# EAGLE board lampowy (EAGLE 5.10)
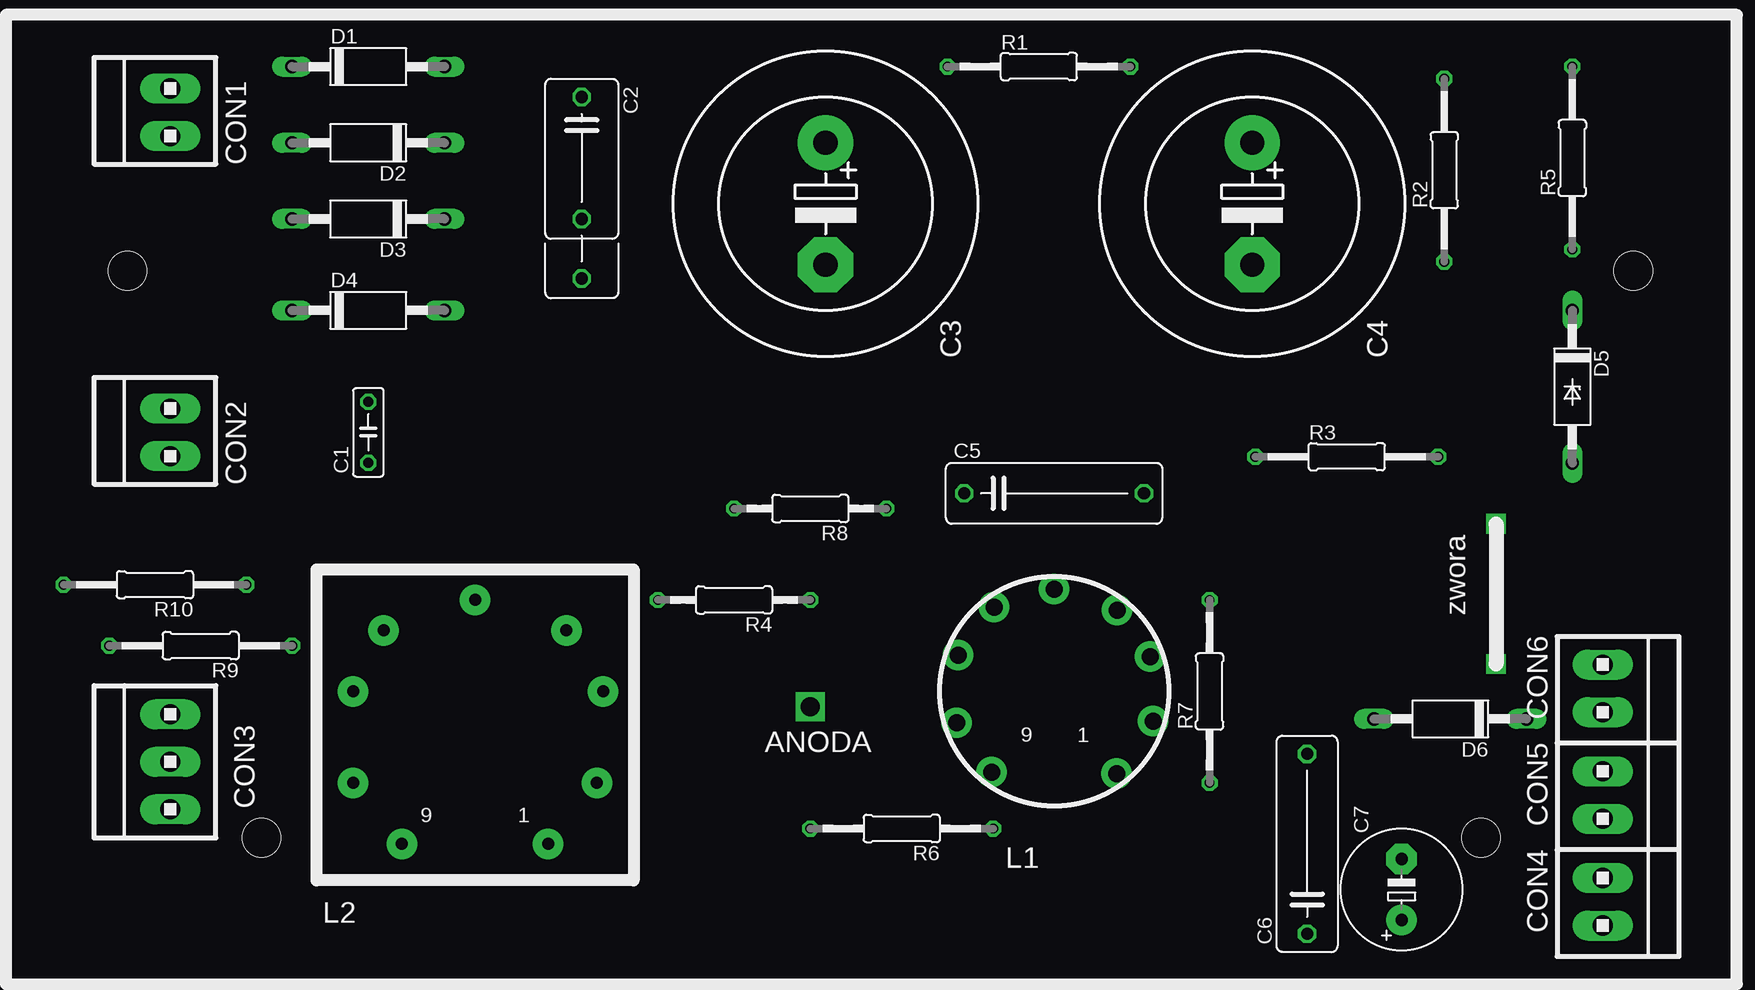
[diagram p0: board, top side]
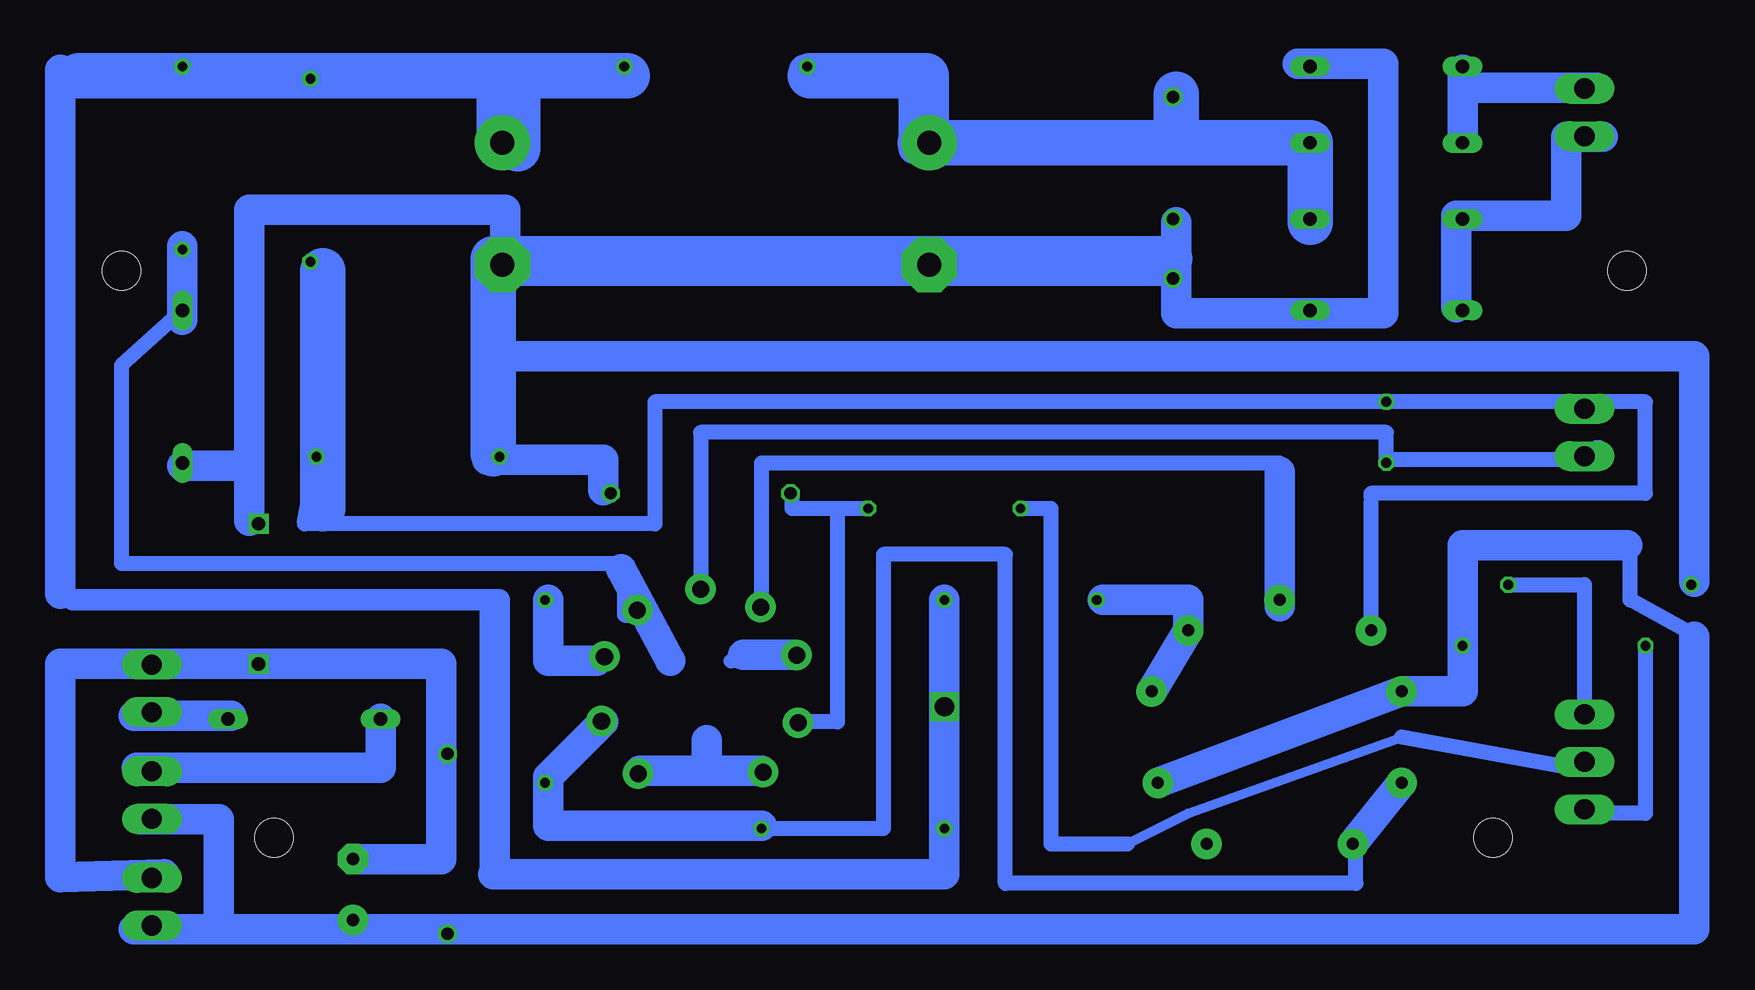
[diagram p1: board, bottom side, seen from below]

No outline drawn. Coordinates in mm, seen from the top.
Copper layers (1*16): Top 0.035mm / dielectric 1.5mm / Bottom 0.035mm
Design rules "default": minimum track width 10mil, minimum drill 24mil, track to track 8mil, track to pad 8mil, pad to pad 8mil, via to via 8mil, smd to smd 8mil, copper to edge 40mil, drill to drill 8mil, minimum pad ring 10mil, minimum via ring 8mil, stop-mask expansion 4mil, vias tented up to drill 0mil, thermal gap 10mil
Holes 3.2 mm at 10.16,59.44 135.64,59.44 122.94,12.19 21.34,12.19

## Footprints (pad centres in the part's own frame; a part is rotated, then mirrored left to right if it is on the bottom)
C050-025X075 = drill 0.813 octagon: 1 -2.54,0; 2 2.54,0
C102_152-062X184 = drill 1.016 octagon: 1 -5.08,0; 2 5.08,0; 3 10.033,0
EB25D = drill 2.007 pad 4.597 round: + -5.08,0 | drill 2.007 pad 4.597 octagon: - 5.08,0
C150-054X183 = drill 1.016 octagon: 1 -7.493,0; 2 7.493,0
E5-10,5 = drill 1.016 pad 2.54 round: + -2.54,0 | drill 1.016 pad 2.54 octagon: - 2.54,0
1X2MTA = drill 1.676 long: 1 1.981,0; 2 -1.981,0
1X3MTA = drill 1.676 long: 1 3.937,0; 2 -0.025,0; 3 -3.988,0
P1-12E = drill 1.118 long: A 6.35,0; C -6.35,0
P1Z12 = drill 1.118 long: A 6.35,0; C -6.35,0
NOVAL = drill 1.422 pad 2.54 round: 1 5.207,-6.858; 2 8.254,-2.484; 3 8.004,2.893; 4 5.258,6.77; 5 0,8.524; 6 -5.004,7.024; 7 -8.004,3.02; 8 -8.127,-2.611; 9 -5.207,-6.731
MAGNOWAL = drill 1 pad 2.54 round: P$1 0,-10.16; P$2 6.096,10.16; P$3 -6.096,10.16; P$4 -10.16,5.08; P$5 10.16,5.08; P$6 10.16,-2.54; P$7 -10.668,-2.54; P$8 -7.62,-7.62; P$9 7.62,-7.62
0207/15 = drill 0.813 octagon: 1 -7.62,0; 2 7.62,0
0207/12 = drill 0.813 octagon: 1 -6.35,0; 2 6.35,0

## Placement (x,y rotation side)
C1  [C050-025X075]  30.23,45.97 90 top
C2  [C102_152-062X184]  48.01,68.83 270 top
C3  [EB25D]  68.33,65.02 270 top
C4  [EB25D]  103.89,65.02 270 top
C5  [C150-054X183]  87.38,40.89 0 top
C6  [C150-054X183]  108.46,11.68 90 top
C7  [E5-10,5]  116.33,7.87 90 top
CON1  [1X2MTA]  13.72,72.64 90 top
CON2  [1X2MTA]  13.72,45.97 90 top
CON3  [1X3MTA]  13.72,18.54 90 top
CON4  [1X2MTA]  133.1,6.86 270 top
CON5  [1X2MTA]  133.1,15.75 270 top
CON6  [1X2MTA]  133.1,24.64 270 top
D1  [P1-12E]  30.23,76.45 0 top
D2  [P1-12E]  30.23,70.1 180 top
D3  [P1-12E]  30.23,63.75 180 top
D4  [P1-12E]  30.23,56.13 0 top
D5  [P1Z12]  130.56,49.78 270 top
D6  [P1-12E]  120.4,22.1 180 top
L1  [NOVAL]  87.38,24.38 0 top
L2  [MAGNOWAL]  39.12,21.84 180 top
R1  [0207/15]  86.11,76.45 0 top
R2  [0207/15]  119.89,67.82 90 top
R3  [0207/15]  111.76,43.94 0 top
R4  [0207/12]  60.71,32 180 top
R5  [0207/15]  130.56,68.83 90 top
R6  [0207/15]  74.68,12.95 180 top
R7  [0207/15]  100.33,24.38 90 top
R8  [0207/12]  67.06,39.62 180 top
R9  [0207/15]  16.26,28.19 180 top
R10  [0207/15]  12.45,33.27 180 top

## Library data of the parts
C1-C7 R1-R10 = rcl
CON1-CON6 = con-amp
D1-D6 = diode
L1 L2 = tubes

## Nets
S$1: D1.C D2.A
S$2: D3.A D4.C
S$3: C2.1 C3.+ D2.C D3.C
S$4: C2.2 D1.A D4.A
S$5: C1.2 R2.1 R3.2
S$6: R8.1
S$7: R1.1
S$8: R8.2
S$9: D5.C R5.1
S$11: L2.P$1
S$14: R7.2
S$15: R4.1 R6.2
S$16: L2.P$2 L2.P$5 R7.1
S$17: C1.1
S$18: L2.P$7 L2.P$8 R4.2
S$22: R10.1
S$24: R9.2
S$27: D6.A
S$28: C7.-
S$42: C4.+ R1.2 R2.2 R5.2
S$44: R3.1 R10.2
S$45: L2.P$4 L2.P$6 R9.1
S$47: D5.A
S$54: L2.P$9

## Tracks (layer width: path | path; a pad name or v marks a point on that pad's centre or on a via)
S$1
  Bottom 1.27: D1.C 23.88,76.2 23.88,75.18 | 23.88,75.18 23.88,74.68 | 23.88,70.61 D2.A | 12.45,75.18 23.88,75.18
  Bottom 2.54: 12.7,74.68 23.88,74.68 | 23.88,74.68 23.88,76.2 | 23.88,74.68 23.88,70.61
S$2
  Bottom 1.27: D4.C D3.A 14.99,63.75 14.99,70.1
S$3
  Bottom 1.27: D2.C D3.C | 47.75,70.1 48.01,70.1 | 48.01,70.1 C2.1 | C3.+ 48.01,70.1
  Bottom 3.81: 36.58,63.5 D2.C 47.75,70.1 | 47.75,70.1 68.58,70.1 | 68.58,70.1 69.09,70.1 | 47.75,74.17 47.75,70.1 | 68.58,70.1 68.58,75.69 78.23,75.69
S$4
  Bottom 1.27: 48.01,59.94 C2.2 | 48.01,59.94 103.89,59.94 | 48.01,59.94 48.01,56.13 D4.A 30.23,56.13 30.23,76.45 D1.A
S$5
  Bottom 1.27: 13.72,48.51 C1.2 91.19,48.51 91.19,38.35 120.4,38.35 R3.2 R2.1
S$6
  Bottom 1.27: R8.1 79.76,39.62 79.76,40.89
S$7
  Bottom 1.27: 69.6,70.1 69.6,76.2 69.6,76.45 R1.1
  Bottom 2.54: 69.6,69.6 69.6,76.2 78.74,76.2
S$8
  Bottom 0.813: 51.82,11.68 46.74,14.22 28.96,20.57
  Bottom 1.27: R8.2 58.17,39.62 58.17,11.68 51.82,11.68 | 14.99,18.03 28.96,20.57
S$9
  Bottom 1.27: R5.1 D5.C 135.64,51.56 135.64,35.05 93.73,35.05 93.73,30.73 92.46,30.73 89.92,26.92
  Bottom 2.54: 89.92,26.92 93.98,34.54
S$10
  Bottom 3.81: 48.26,60.45 104.65,60.45 104.65,44.2
S$11
  Bottom 1.27: 82.3,32 82.3,43.43 39.12,43.43 39.12,42.67 L2.P$1
  Bottom 2.54: 39.12,31.5 39.12,42.67
S$12
  Bottom 1.27: 79.76,26.92 84.84,26.92
S$13
  Bottom 1.27: 31.5,40.64 31.5,40.89 8.64,40.89 8.64,48.51 12.45,48.51
S$14
  Bottom 1.27: 95,26.92 96.01,26.92 | 100.08,26.92 100.33,26.92 R7.2
  Bottom 2.54: 96.01,26.92 100.08,26.92 100.08,32
S$15  (via drill 1.6)
  Bottom 1.27: 105.16,32 105.16,9.14 104.65,9.14 | R4.1 v67.06,23.11 R6.2 67.06,9.14
  Bottom 2.54: R4.1 67.06,9.14 104.65,9.14
S$16
  Bottom 1.27: L2.P$5 32.77,11.68 32.77,8.38 61.98,8.38 61.98,35.81 72.14,35.81 72.14,12.95 100.33,12.95 R7.1 95,21.84
  Bottom 2.54: L2.P$5 L2.P$2
S$17
  Bottom 1.27: 87.38,33.27 87.38,45.97 30.23,45.97 C1.1
S$18
  Bottom 1.27: L2.P$8 49.28,24.38 | R4.2 53.85,32 | 46.74,31.5 46.74,30.73
  Bottom 2.54: L2.P$7 L2.P$8 46.74,31.5 46.74,32 53.85,32
S$19
  Bottom 2.54: 82.3,17.78 86.87,17.78 | 92.46,17.78 86.87,17.78 | 86.87,17.78 86.87,20.32
S$20
  Bottom 1.27: 4.83,4.06 134.37,4.06
S$21
  Bottom 1.27: 78.49,21.84 75.95,21.84 75.95,39.62
S$22
  Bottom 1.27: R10.1 13.72,33.27 13.72,21.84
S$23
  Bottom 1.27: 87.38,18.03 92.46,18.03 | 87.38,18.03 87.38,20.57 | 82.3,18.03 87.38,18.03
S$24
  Bottom 1.27: R9.2 8.64,14.22 12.45,14.22
S$25
  Bottom 1.27: 134.37,5.33 131.83,5.33
S$26
  Bottom 2.54: 79.76,27.43 83.82,27.43
S$27
  Bottom 2.54: D6.A 114.05,18.03 134.37,18.03
S$28  (via drill 1.1)
  Bottom 2.54: 132.08,9.14 140.72,8.89 140.72,26.67 v124.21,26.67 108.97,26.67 108.97,10.41 C7.-
S$29
  Bottom 1.27: 95,40.89 95,43.43
S$30
  Bottom 2.54: 126.49,22.35 134.62,22.35
S$31
  Bottom 2.54: 127.51,4.57 4.57,4.57 4.57,28.96 | 127.51,4.57 134.62,4.57 | 127.51,4.57 127.51,13.72 134.11,13.72
S$32
  Bottom 2.54: 12.19,70.61 15.24,70.61 15.24,64.01 24.38,64.01 24.38,56.39
S$33
  Bottom 2.54: 47.75,73.66 47.75,70.61
S$34
  Bottom 2.54: 37.59,76.71 30.48,76.71 30.48,55.88 47.75,55.88 47.75,63.5
S$35
  Bottom 2.54: 48.26,59.44 103.63,59.44 | 103.63,59.44 104.14,59.44 | 103.63,59.44 103.63,64.52 124.97,64.52 124.97,38.61
S$36
  Bottom 2.54: 93.47,76.2 139.19,76.2
S$37
  Bottom 2.54: 104.14,74.17 104.14,75.18
  Bottom 3.81: 104.14,70.1 104.14,74.17
S$38
  Bottom 2.54: 125.98,43.18 130.56,43.18
S$39
  Bottom 2.54: 130.56,61.47 130.56,55.37
S$40
  Bottom 2.54: 82.3,13.21 100.08,13.21 100.08,17.27 95.5,21.84
S$41
  Bottom 1.778: 104.14,9.65 104.14,32 139.7,32
S$42
  Bottom 1.27: 139.45,76.45 R5.2 R2.2 103.89,76.45 | 103.89,76.45 C4.+ | R1.2 103.89,76.45
S$43
  Bottom 2.54: 140.72,76.2 140.72,32.51
S$44
  Bottom 1.27: 105.16,43.69 R3.1 | 105.16,58.67 105.16,52.32 4.83,52.32 R10.2
  Bottom 2.54: 95.5,41.15 95.5,43.69 105.16,43.69 105.16,52.32 | 4.57,33.53 4.57,52.32 105.16,52.32 | 105.16,52.32 105.16,59.94
S$45
  Bottom 1.27: 23.88,24.38 R9.1 23.88,36.58 23.88,37.08 9.91,37.08 9.91,32 4.32,28.96
  Bottom 2.54: L2.P$4 L2.P$6 23.88,24.38 23.88,36.58 10.16,36.58
S$46
  Bottom 3.81: 93.47,75.69 139.19,75.69
S$47  (via drill 1.1)
  Bottom 1.27: D5.A 125.48,43.43 125.48,38.35 v124.21,38.35
S$48  (via drill 1.5)
  other vias: 122.94,12.19
S$49  (via drill 1.5)
  other vias: 21.34,12.19
S$50  (via drill 1.5)
  other vias: 10.16,59.44
S$51  (via drill 1.5)
  other vias: 135.64,59.44
S$52
  Bottom 3.81: 102.62,69.6 102.62,74.17
S$53
  Bottom 3.81: 118.87,59.44 118.87,39.62
S$54
  Bottom 1.27: L2.P$9 31.5,40.13
S$55
  Bottom 1.27: 12.45,44.7 12.7,44.7
S$56
  Bottom 1.27: 14.22,43.69 29.97,43.69

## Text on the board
tNames: zwora | ANODA | L2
